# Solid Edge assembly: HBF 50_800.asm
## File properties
Title: Zylinder
Author: ahadarics
Template: iso assembly.asm
Last saved by: ahadarics
Revision: 51
Application: Solid Edge
Username: ahadarics
Dokumentum tartalom típus: 1
Document Number: HBF 50/800
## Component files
Kit.par
Profilrohr 50_800.par
Kolbenstange_1_50_800.par
Mutter.par
Kolbenstange_2_50_800.par
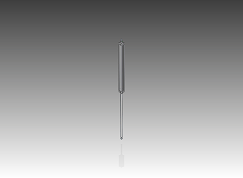
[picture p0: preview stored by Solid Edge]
